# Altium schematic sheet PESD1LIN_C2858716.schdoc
size 127 x 101 mm
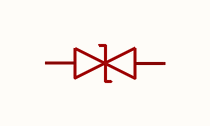
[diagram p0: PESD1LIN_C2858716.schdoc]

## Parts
D?  pesd1lin_c2858716  [SOD-323_L1.7-W1.3-LS2.5-BI-A]  (value not drawn)

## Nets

Not connected (* = marked no-connect by the designer): D? 1 2

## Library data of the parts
D? = pesd1lin_c2858716: 极性:双向;反向截止电压(Vrwm):15V；24V;钳位电压:70V；44V;峰值脉冲电流(Ipp):-;峰值脉冲功率(Ppp):160W@8/20us;击穿电压:30.3V；20.3V;; Manufacturer: TECH PUBLIC(台舟); AddInBom: yes; ModelId: 7ab958ea97e1446fa8eaaf4c2265caaf; ModelTransform: 98.425,49.247,0,0,0,0,0,0,0; Polarity: 双向; Reverse Leakage Current (Ir): 50nA; Number of Channels: 单路; level of protection: IEC 61000-4-2；IEC 61000-4-4; Type: ESD; Junction Capacitance: 13pF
